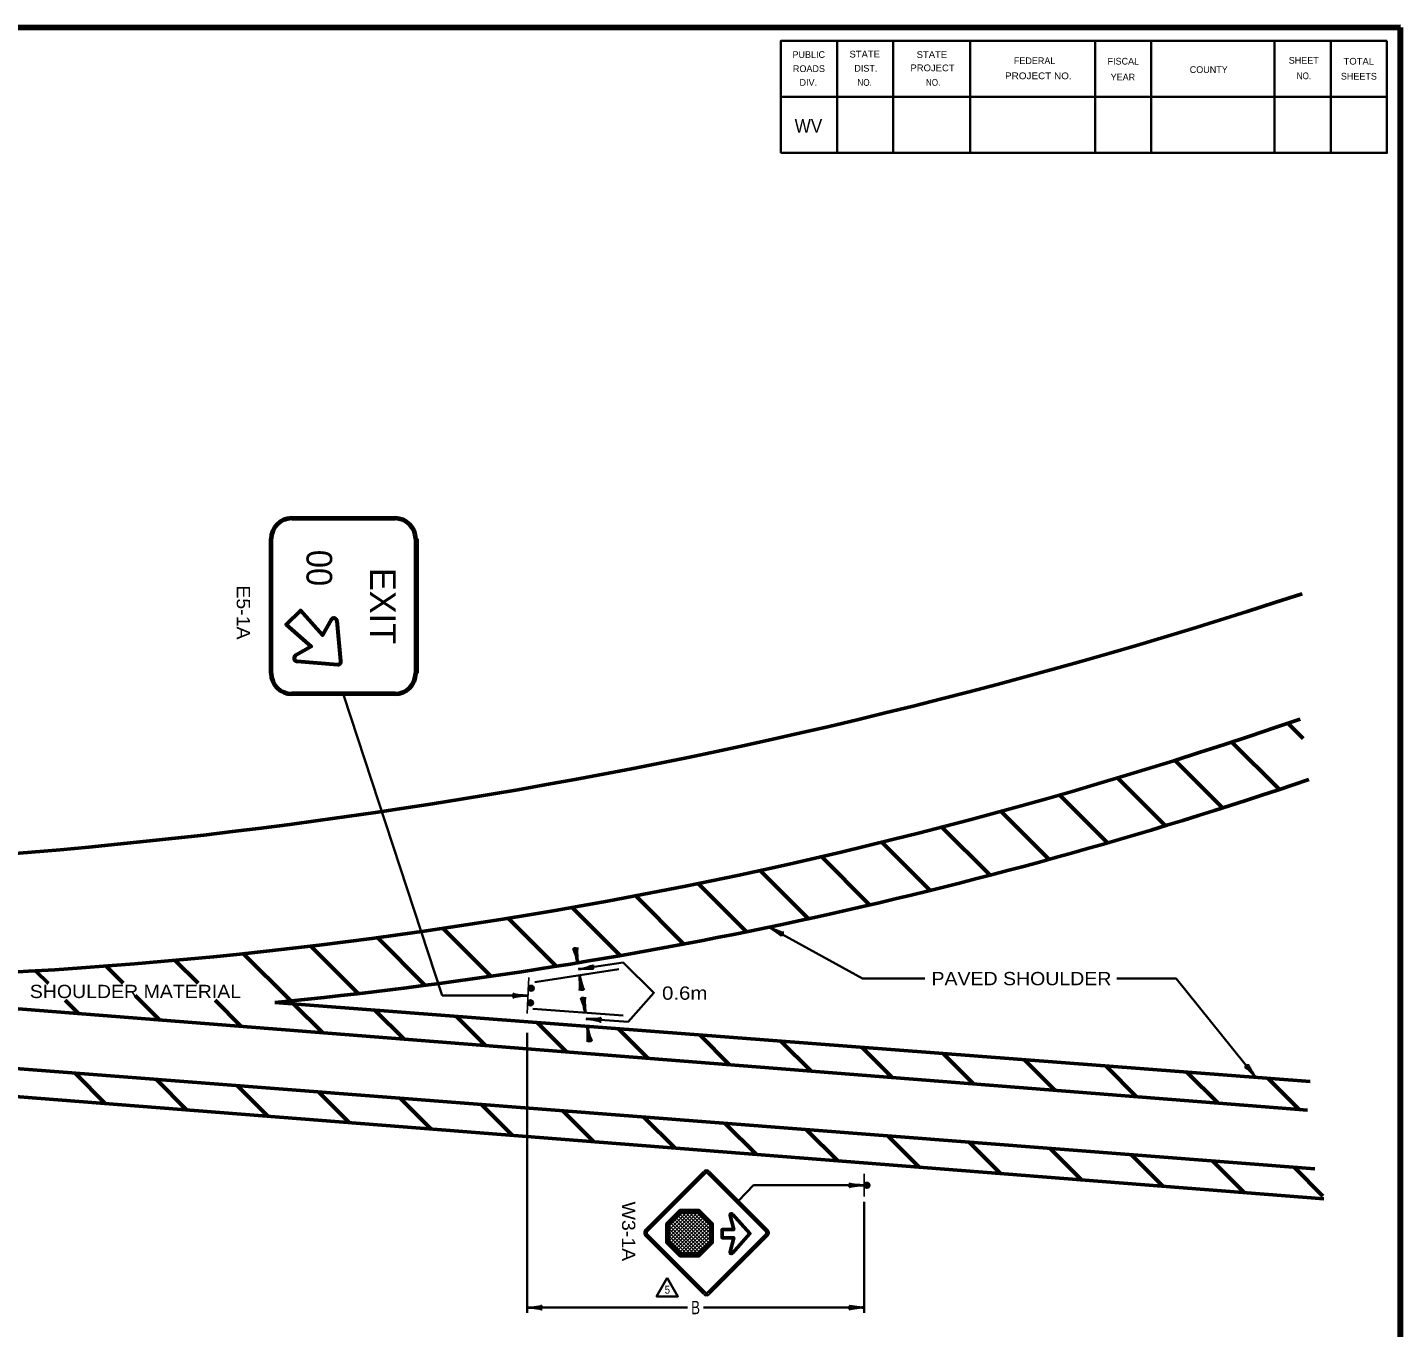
# Model space of a CAD drawing. Extents: x -371 to 484, y -338 to 206.
# Drawn here: x 166.8 to 477.5, y -94.6 to 199.6 of the extents above; entities that cross this region are included whole.
import ezdxf
from ezdxf.enums import TextEntityAlignment as Align

# ---------------------------------------------------------------- set-up
doc = ezdxf.new("R2010")
doc.units = 0
for name, color, linetype, lineweight in [('1', 7, 'Continuous', 53), ('4', 7, 'Continuous', 25), ('61', 7, 'Continuous', 35)]:
    doc.layers.add(name, color=color, linetype=linetype, lineweight=lineweight)
doc.layers.add('2', color=7, linetype='Continuous')

msp = doc.modelspace()

# ---------------------------------------------------------------- hatches: boundary and pattern name
at = {"layer": '4'}
for points in [[(280.803, -17.187, 1), (280.74, -18.497, 1)], [(280.64, -20.473, 1), (280.577, -21.784, 1)], [(356.748, -63.075, 1), (356.748, -61.763, 1)]]:
    msp.add_hatch(color=256, dxfattribs=at).paths.add_polyline_path(points)

# ---------------------------------------------------------------- linework, layer by layer
at = {"layer": '1', "lineweight": 158}
msp.add_line((477.495, -326.494), (477.495, 199.606), dxfattribs=at)
at = {"layer": '1', "lineweight": 13}
for p, q in [((477.495, -326.494), (477.495, 199.606)), ((226.579, 88.739), (249.964, 88.739)), ((221.692, 53.452), (221.692, 83.852)), ((249.964, 48.564), (226.579, 48.564)), ((306.462, -72.699), (319.973, -59.188)), ((320.939, -59.188), (334.45, -72.699)), ((319.973, -87.176), (306.462, -73.665)), ((334.45, -73.665), (320.939, -87.176))]:
    msp.add_line(p, q, dxfattribs=at)
at = {"layer": '1', "lineweight": 70}
for p, q in [((226.579, 88.529), (249.964, 88.529)), ((221.902, 53.452), (221.902, 83.852)), ((254.641, 83.852), (254.641, 53.452)), ((254.851, 83.852), (254.851, 53.452)), ((249.964, 48.775), (226.579, 48.775)), ((306.784, -72.739), (320.014, -59.509)), ((320.898, -59.509), (334.129, -72.739)), ((320.014, -86.854), (306.784, -73.624)), ((334.129, -73.624), (320.898, -86.854))]:
    msp.add_line(p, q, dxfattribs=at)
at = {"layer": '1', "lineweight": 60}
for p, q in [((237.709, 56.199), (236.849, 65.26)), ((227.787, 56.166), (236.915, 55.405))]:
    msp.add_line(p, q, dxfattribs=at)
at = {"layer": '1', "lineweight": 35}
for p, q in [((238.272, 48.564), (260.624, -19.494)), ((355.738, -15.639), (334.647, -3.986)), ((290.722, -8.526), (291.27, -12.084)), ((291.495, -13.54), (301.595, -11.984)), ((281.599, -16.422), (300.613, -13.493)), ((291.699, -14.867), (292.247, -18.425)), ((355.738, -15.639), (369.854, -15.639)), ((413.302, -15.639), (426.732, -15.639)), ((426.732, -15.639), (444.759, -38.021)), ((280.027, -19.494), (260.624, -19.494)), ((292.454, -19.771), (293.003, -23.329)), ((281.108, -22.46), (301.62, -23.959)), ((293.221, -24.743), (302.715, -25.437)), ((279.824, -27.936), (279.824, -91.289)), ((293.482, -26.442), (294.03, -30)), ((327.694, -65.943), (331.075, -62.419)), ((356.108, -62.419), (331.075, -62.419)), ((356.108, -66.179), (356.108, -91.289)), ((279.824, -90.089), (316.166, -90.089)), ((319.766, -90.089), (356.108, -90.089))]:
    msp.add_line(p, q, dxfattribs=at)
at = {"layer": '1'}
for p, q in [((455.434, 38.726), (451.991, 42.169)), ((449.994, 27.196), (439.215, 37.974)), ((437.212, 23.007), (426.44, 33.779)), ((424.191, 19.058), (413.397, 29.851)), ((411.169, 15.109), (400.299, 25.979)), ((397.885, 11.423), (387.044, 22.263)), ((384.525, 7.812), (373.612, 18.725)), ((370.99, 4.376), (360.128, 15.239)), ((357.281, 1.115), (346.351, 12.045)), ((343.475, -2.05), (332.574, 8.851)), ((315.303, -7.819), (304.348, 3.136)), ((329.402, -4.948), (318.483, 5.972)), ((300.851, -10.338), (289.972, 0.541)), ((286.4, -12.857), (275.464, -1.922)), ((271.584, -15.012), (260.779, -4.207)), ((241.553, -18.922), (230.856, -8.225)), ((256.738, -17.137), (245.882, -6.281)), ((205.389, -16.699), (200.153, -11.463)), ((226.293, -20.633), (215.553, -9.892)), ((171.522, -16.774), (168.608, -13.859)), ((188.416, -16.697), (184.422, -12.703)), ((76.814, -15.591), (456.428, -45.449)), ((178.324, -23.575), (175.295, -20.547)), ((196.743, -25.024), (191.167, -19.448)), ((215.163, -26.473), (209.24, -20.55)), ((457.066, -38.963), (222.76, -21.029)), ((233.582, -27.921), (227.015, -21.355)), ((252.001, -29.37), (245.392, -22.761)), ((270.421, -30.819), (263.77, -24.168)), ((288.84, -32.268), (282.147, -25.575)), ((307.259, -33.716), (300.524, -26.981)), ((325.678, -35.165), (318.901, -28.388)), ((344.098, -36.614), (337.278, -29.794)), ((362.517, -38.063), (355.655, -31.201)), ((380.936, -39.511), (374.033, -32.608)), ((399.356, -40.96), (392.41, -34.014)), ((184.459, -43.957), (177.562, -37.06)), ((417.775, -42.409), (410.787, -35.421)), ((436.194, -43.858), (429.164, -36.828)), ((202.868, -45.396), (195.952, -38.479)), ((221.278, -46.835), (214.342, -39.899)), ((454.614, -45.306), (447.541, -38.234)), ((239.688, -48.274), (232.732, -41.318)), ((258.098, -49.713), (251.123, -42.738)), ((276.507, -51.152), (269.513, -44.158)), ((294.917, -52.592), (287.903, -45.577)), ((313.327, -54.031), (306.293, -46.997)), ((331.737, -55.47), (324.683, -48.416)), ((350.146, -56.909), (343.073, -49.836)), ((368.556, -58.348), (361.464, -51.256)), ((386.966, -59.787), (379.854, -52.675)), ((405.376, -61.227), (398.244, -54.095)), ((423.785, -62.666), (416.634, -55.515)), ((442.195, -64.105), (435.024, -56.934)), ((459.909, -64.848), (453.415, -58.354)), ((325.786, -69.232), (326.615, -72.438))]:
    msp.add_line(p, q, dxfattribs=at)
at = {"layer": '1', "lineweight": 25}
for p, q in [((280.23, -15.419), (279.824, -23.569)), ((311.693, -71.981), (315.333, -68.341)), ((311.693, -72.808), (316.159, -68.341)), ((311.693, -73.634), (316.986, -68.341)), ((311.693, -74.461), (317.813, -68.341)), ((311.693, -75.288), (318.639, -68.341)), ((321.539, -75.22), (314.661, -68.341)), ((321.539, -74.393), (315.487, -68.341)), ((321.539, -73.566), (316.314, -68.341)), ((321.539, -72.739), (317.141, -68.341)), ((321.539, -71.913), (317.968, -68.341)), ((318.688, -78.156), (311.724, -71.191)), ((312.1, -75.707), (319.062, -68.746)), ((319.101, -77.743), (312.137, -70.778)), ((312.513, -76.121), (319.475, -69.159)), ((319.514, -77.329), (312.55, -70.365)), ((312.926, -76.535), (319.889, -69.572)), ((319.927, -76.915), (312.964, -69.951)), ((313.339, -76.949), (320.302, -69.986)), ((320.34, -76.501), (313.377, -69.538)), ((313.752, -77.363), (320.715, -70.399)), ((320.753, -76.087), (313.79, -69.125)), ((314.164, -77.777), (321.129, -70.812)), ((321.166, -75.673), (314.204, -68.711)), ((314.581, -78.187), (321.539, -71.229)), ((317.893, -78.187), (311.693, -71.988)), ((317.066, -78.187), (311.693, -72.814)), ((316.239, -78.187), (311.693, -73.641)), ((315.412, -78.187), (311.693, -74.468)), ((315.408, -78.187), (321.539, -72.056)), ((316.234, -78.187), (321.539, -72.883)), ((317.061, -78.187), (321.539, -73.709)), ((317.888, -78.187), (321.539, -74.536)), ((314.585, -78.187), (311.693, -75.294))]:
    msp.add_line(p, q, dxfattribs=at)
at = {"layer": '1', "lineweight": 158}
msp.add_lwpolyline([(477.495, 199.606), (-314.205, 199.506), (-314.105, -326.494)], dxfattribs=at)
at = {"layer": '1', "lineweight": 60}
msp.add_lwpolyline([(235.509, 65.541), (233.558, 62.102), (228.531, 67.691), (225.324, 64.483), (230.946, 59.522), (227.49, 57.522)], dxfattribs=at)
at = {"layer": '1'}
for points in [[(-289.357, -11.407), (-102.62, -15.431), (458.068, -58.713)], [(460.106, -65.505), (-7.77, -28.929), (-289.578, -23.989)], [(323.971, -72.438), (326.615, -72.438), (325.786, -69.232)], [(326.293, -68.964), (330.273, -73.359), (326.293, -77.763)], [(326.293, -77.763), (330.273, -73.359), (326.293, -68.964)], [(325.786, -77.487), (326.615, -74.29), (323.971, -74.29), (323.971, -72.438)], [(326.615, -72.438), (323.971, -72.438), (323.971, -74.29), (326.615, -74.29), (325.786, -77.487)]]:
    msp.add_lwpolyline(points, dxfattribs=at)
at = {"layer": '1', "lineweight": 35}
msp.add_lwpolyline([(301.595, -11.984), (308.525, -18.852), (302.715, -25.437)], dxfattribs=at)
for points in [[(311.347, -71.078), (314.436, -67.996), (318.796, -67.996), (321.884, -71.078), (321.884, -75.444), (318.796, -78.533), (314.436, -78.533), (311.347, -75.444)], [(311.553, -83.391), (309.153, -87.548), (313.953, -87.548)]]:
    msp.add_lwpolyline(points, close=True, dxfattribs=at)
at = {"layer": '1', "lineweight": 70}
msp.add_lwpolyline([(311.693, -71.223), (314.574, -68.341), (318.658, -68.341), (321.539, -71.223), (321.539, -75.299), (318.658, -78.187), (314.574, -78.187), (311.693, -75.299)], close=True, dxfattribs=at)
at = {"layer": '1', "lineweight": 13}
for centre, radius, start, end in [((226.579, 83.852), 4.887, 90, 180), ((249.964, 83.852), 4.887, 0, 90), ((226.579, 53.452), 4.887, 180, 270), ((249.964, 53.452), 4.887, 270, 0), ((320.456, -59.67), 0.682, 45, 135), ((306.944, -73.182), 0.682, 135, 225), ((333.968, -73.182), 0.682, 315, 45), ((320.456, -86.693), 0.682, 225, 315)]:
    msp.add_arc(centre, radius, start, end, dxfattribs=at)
at = {"layer": '1', "lineweight": 70}
for centre, radius, start, end in [((226.579, 83.852), 4.677, 90, 180), ((249.964, 83.852), 4.677, 0, 90), ((226.579, 53.452), 4.677, 180, 270), ((249.964, 53.452), 4.677, 270, 0), ((320.456, -59.951), 0.626, 45, 135), ((307.226, -73.182), 0.626, 135, 225), ((333.686, -73.182), 0.626, 315, 45), ((320.456, -86.412), 0.626, 225, 315)]:
    msp.add_arc(centre, radius, start, end, dxfattribs=at)
at = {"layer": '1'}
for centre, radius, start, end in [((62.954, 1263.937), 1255.341, 269.11133, 288.21006), ((102.852, 1063.378), 1079.284, 268.61761, 289.03246), ((123.149, 1008.711), 1034.547, 275.52525, 288.81251), ((326.073, -69.161), 0.296, 42.58363, 194.30223), ((326.073, -69.161), 0.296, 42.58363, 194.30223), ((326.073, -77.562), 0.296, 165.69778, 317.41638), ((326.073, -77.562), 0.296, 165.69778, 317.41638)]:
    msp.add_arc(centre, radius, start, end, dxfattribs=at)
at = {"layer": '1', "lineweight": 60}
for centre, start, end in [((236.13, 65.183), 5.43005, 150.55122), ((227.845, 56.886), 120.11373, 265.25762), ((236.984, 56.13), 265.25653, 5.40471)]:
    msp.add_arc(centre, 0.725, start, end, dxfattribs=at)
at = {"layer": '1', "lineweight": 40}
for centre, major_axis, ratio, start_param, end_param in [((335.701, -4.859), (-1.743, 1.204), 0.07063, 3.1407148, 5.41811), ((335.701, -4.859), (-1.743, 1.204), 0.07063, 3.1407148, 5.41811), ((335.954, -4.329), (-1.966, 0.872), 0.122415, 0.8963533, 3.1415927), ((335.954, -4.329), (-1.966, 0.872), 0.122415, 0.8963533, 3.1415927), ((290.743, -10.84), (0.511, -2.089), 0.122415, 0.8963533, 3.1415927), ((291.317, -10.716), (0.113, -2.115), 0.07063, 3.1407148, 5.41811), ((292.738, -13.013), (-2.089, -0.511), 0.122415, 0.8963533, 3.1415927), ((292.738, -13.013), (-2.089, -0.511), 0.122415, 0.8963533, 3.1415927), ((292.862, -13.586), (-2.115, -0.113), 0.07063, 3.1407148, 5.41811), ((292.862, -13.586), (-2.115, -0.113), 0.07063, 3.1407148, 5.41811), ((291.653, -16.234), (-0.113, 2.115), 0.07063, 3.1407148, 5.41811), ((292.226, -16.11), (-0.511, 2.089), 0.122415, 0.8963533, 3.1415927), ((278.718, -19.826), (2.143, 0.187), 0.122415, 0.8963533, 3.1415927), ((278.682, -19.24), (2.108, -0.211), 0.07063, 3.1407148, 5.41811), ((292.476, -22.085), (0.511, -2.089), 0.122415, 0.8963533, 3.1415927), ((293.049, -21.962), (0.113, -2.115), 0.07063, 3.1407148, 5.41811), ((294.543, -25.094), (-2.087, 0.364), 0.07063, 3.1407148, 5.41811), ((294.551, -24.508), (-2.151, -0.031), 0.122415, 0.8963533, 3.1415927), ((293.436, -27.81), (-0.113, 2.115), 0.07063, 3.1407148, 5.41811), ((294.009, -27.686), (-0.511, 2.089), 0.122415, 0.8963533, 3.1415927), ((443.68, -37.209), (1.49, -1.551), 0.122415, 0.8963533, 3.1415927), ((444.114, -36.815), (1.158, -1.774), 0.07063, 3.1407148, 5.41811), ((354.763, -62.165), (2.108, -0.211), 0.07063, 3.1407148, 5.41811), ((354.799, -62.751), (2.143, 0.187), 0.122415, 0.8963533, 3.1415927), ((281.169, -90.343), (-2.108, 0.211), 0.07063, 3.1407148, 5.41811), ((281.169, -90.343), (-2.108, 0.211), 0.07063, 3.1407148, 5.41811), ((281.134, -89.757), (-2.143, -0.187), 0.122415, 0.8963533, 3.1415927), ((281.134, -89.757), (-2.143, -0.187), 0.122415, 0.8963533, 3.1415927), ((354.799, -90.42), (2.143, 0.187), 0.122415, 0.8963533, 3.1415927), ((354.763, -89.835), (2.108, -0.211), 0.07063, 3.1407148, 5.41811)]:
    msp.add_ellipse(centre, major_axis=major_axis, ratio=ratio, start_param=start_param, end_param=end_param, dxfattribs=at)
at = {"layer": '4'}
msp.add_line((356.108, -59.859), (356.108, -64.979), dxfattribs=at)
for centre in [(280.771, -17.842), (280.608, -21.129), (356.748, -62.419)]:
    msp.add_circle(centre, 0.656, dxfattribs=at)
at = {"layer": '61'}
for p, q in [((349.995, 196.606), (349.995, 171.206)), ((362.695, 196.606), (362.695, 171.206)), ((380.095, 196.606), (380.095, 171.206)), ((408.395, 196.606), (408.395, 171.206)), ((421.095, 196.606), (421.095, 171.206)), ((448.995, 196.606), (448.995, 171.206)), ((461.695, 196.606), (461.695, 171.206)), ((474.395, 183.906), (337.295, 183.906))]:
    msp.add_line(p, q, dxfattribs=at)
for points in [[(474.395, 196.606), (337.295, 196.606), (337.295, 171.206)], [(474.395, 196.606), (474.395, 171.206), (337.295, 171.206)]]:
    msp.add_lwpolyline(points, dxfattribs=at)

# ---------------------------------------------------------------- texts
at = {"layer": '1'}
for s, height, width, p in [('WV', 3.048, 0.95, (340.395, 175.806)), ('5', 1.8, 0.9, (310.981, -86.947))]:
    msp.add_text(s, height=height, dxfattribs=dict(at, width=width)).set_placement(p)
at = {"layer": '1', "width": 0.95}
msp.add_text('00', height=5.808, rotation=270, dxfattribs=at).set_placement((229.917, 77.285), align=Align.CENTER)
at = {"layer": '1'}
msp.add_text('EXIT', height=5.808, rotation=270, dxfattribs=at).set_placement((244.312, 68.675), align=Align.CENTER)
for s, width, p in [('PAVED SHOULDER', 1.1, (391.709, -17.139)), ('SHOULDER MATERIAL', 1.1, (191.217, -20.05)), ('0.6m', 1.15, (315.512, -20.425)), ('B', 0.75, (317.966, -91.589))]:
    msp.add_text(s, height=3, dxfattribs=dict(at, width=width)).set_placement(p, align=Align.CENTER)
at = {"layer": '2', "width": 1.1}
for s, p in [('E5-1A', (214.143, 67.222)), ('W3-1A', (301.324, -72.841))]:
    msp.add_text(s, height=3, rotation=270, dxfattribs=at).set_placement(p, align=Align.CENTER)
at = {"layer": '61'}
for s, height, rotation, p in [('PUBLIC', 1.525, 0.033, (339.895, 192.706)), ('FEDERAL', 1.523, 0.007, (389.995, 191.306)), ('FISCAL', 1.525, 359.942, (411.195, 191.206)), ('SHEET', 1.525, 0.059, (452.195, 191.406)), ('ROADS', 1.525, 0.124, (339.995, 189.506)), ('DIST.', 1.525, 0.056, (353.895, 189.606)), ('COUNTY', 1.523, 0.069, (429.795, 189.306)), ('DIV.', 1.525, 359.932, (341.495, 186.406)), ('YEAR', 1.523, 0.105, (411.895, 187.606)), ('SHEETS', 1.523, 359.959, (463.995, 187.806))]:
    msp.add_text(s, height=height, rotation=rotation, dxfattribs=at).set_placement(p)
for s, rotation, width, p in [('STATE', 0.059, 1.05, (352.795, 192.806)), ('STATE', 0.059, 1.05, (367.995, 192.706)), ('TOTAL', 359.926, 1.05, (464.595, 191.206)), ('PROJECT', 359.908, 1.05, (366.595, 189.706)), ('NO.', 359.852, 0.9, (354.595, 186.406)), ('NO.', 0.225, 0.9, (370.095, 186.406)), ('PROJECT NO.', 359.922, 1.1, (387.995, 187.906)), ('NO.', 359.852, 0.9, (453.995, 187.906))]:
    msp.add_text(s, height=1.525, rotation=rotation, dxfattribs=dict(at, width=width)).set_placement(p)

doc.saveas('drawing.dxf')
